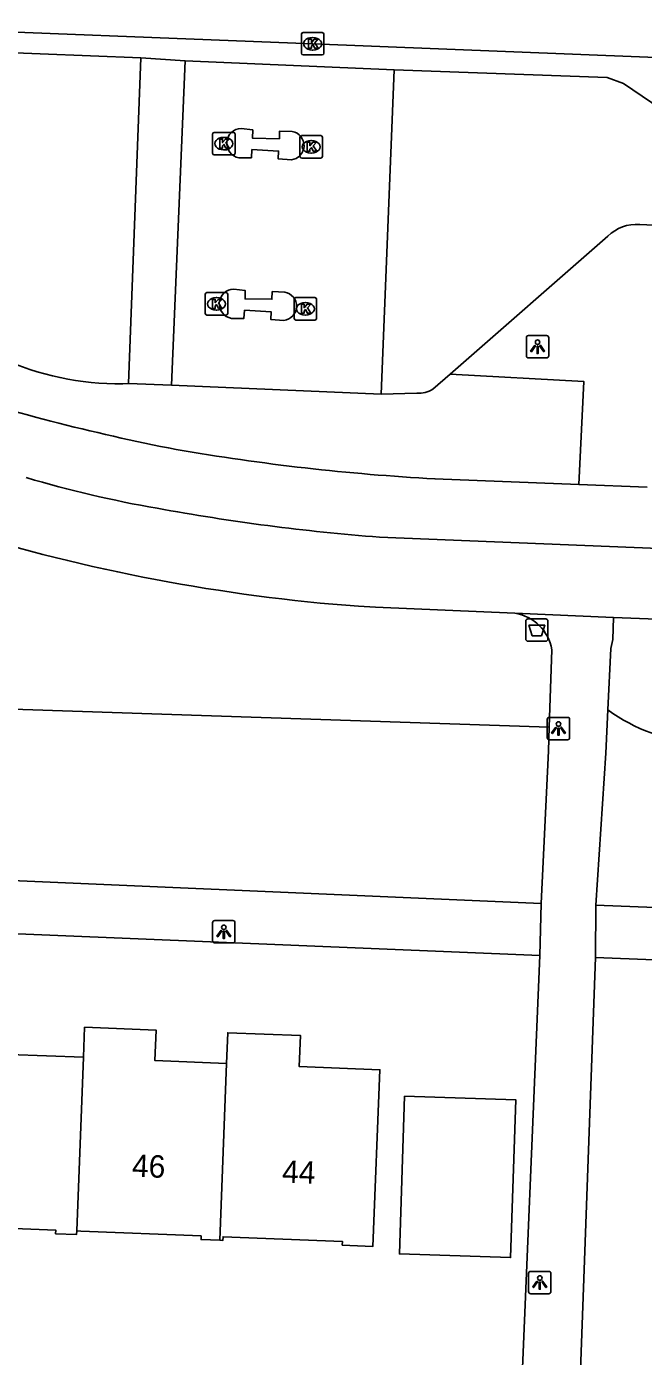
# Model space of a CAD drawing. Extents: x 161355 to 162026, y 386504 to 387459.
# Drawn here: x 161506.1 to 161533.7, y 387396.4 to 387455.8 of the extents above; entities that cross this region are included whole.
import ezdxf

# ---------------------------------------------------------------- set-up
doc = ezdxf.new("R2010")
doc.units = 0
for name, color, linetype in [('IMGEO_Afvalbak', 7, 'Continuous'), ('IMGEO_Fietspad_gesloten', 7, 'Continuous'), ('IMGEO_Groenvoorziening', 7, 'Continuous'), ('IMGEO_Kolk', 7, 'Continuous'), ('IMGEO_Lichtpunt', 7, 'Continuous'), ('IMGEO_Pand', 7, 'Continuous'), ('IMGEO_Pand_nummerreeks', 7, 'Continuous'), ('IMGEO_Rijbaan_lokaal_gesloten', 7, 'Continuous'), ('IMGEO_Rijbaan_lokaal_open', 7, 'Continuous'), ('IMGEO_Voetpad_open', 7, 'Continuous')]:
    doc.layers.add(name, color=color, linetype=linetype)

msp = doc.modelspace()

# ---------------------------------------------------------------- linework, layer by layer
at = {"layer": 'IMGEO_Afvalbak'}
for p, q in [((161528.416, 387428.43), (161528.416, 387429.23)), ((161528.416, 387429.23), (161528.416, 387428.43)), ((161528.516, 387429.33), (161529.306, 387429.33)), ((161529.306, 387429.33), (161528.516, 387429.33)), ((161529.406, 387429.23), (161529.406, 387428.43)), ((161529.406, 387428.43), (161529.406, 387429.23)), ((161529.306, 387428.33), (161528.516, 387428.33)), ((161528.516, 387428.33), (161529.306, 387428.33))]:
    msp.add_line(p, q, dxfattribs=at)
msp.add_lwpolyline([(161528.559, 387429.044), (161529.263, 387429.044), (161529.114, 387428.574), (161528.708, 387428.574), (161528.559, 387429.044)], dxfattribs=at)
for centre, start, end in [((161528.516, 387429.23), 90, 180), ((161528.516, 387429.23), 90, 180), ((161529.306, 387429.23), 0, 90), ((161529.306, 387429.23), 360, 90), ((161528.516, 387428.43), 180, 270), ((161528.516, 387428.43), 180, 270), ((161529.306, 387428.43), 270, 0), ((161529.306, 387428.43), 270, 0)]:
    msp.add_arc(centre, 0.1, start, end, dxfattribs=at)
at = {"layer": 'IMGEO_Fietspad_gesloten'}
for points in [[(161530.79, 387435.322), (161524.366, 387435.573)], [(161533.831, 387435.204), (161530.79, 387435.322)], [(161550.847, 387431.802), (161521.887, 387432.975)]]:
    msp.add_lwpolyline(points, dxfattribs=at)
for centre, radius, start, end in [((161531.28, 387531.263), 96.168, 252.09859, 258.93178), ((161529.933, 387536.124), 100.704, 260.21511, 266.83121), ((161520.95, 387485.839), 52.352, 253.55405, 260.11709), ((161529.21, 387528.19), 95.496, 259.59553, 265.60189)]:
    msp.add_arc(centre, radius, start, end, dxfattribs=at)
at = {"layer": 'IMGEO_Groenvoorziening'}
msp.add_lwpolyline([(161499.222, 387425.612), (161503.74, 387425.354), (161529.46, 387424.501)], dxfattribs=at)
msp.add_arc((161536.51, 387431.29), 7.475, 233.6324, 267.37619, dxfattribs=at)
at = {"layer": 'IMGEO_Kolk'}
for p, q in [((161518.481, 387455.486), (161519.333, 387455.486)), ((161518.406, 387454.56), (161518.406, 387455.412)), ((161518.894, 387455.266), (161518.919, 387455.266)), ((161519.407, 387455.412), (161519.407, 387454.56)), ((161519.333, 387454.486), (161518.481, 387454.486)), ((161518.917, 387454.706), (161518.892, 387454.706)), ((161514.442, 387450.105), (161514.442, 387450.957)), ((161514.517, 387451.031), (161515.369, 387451.031)), ((161514.93, 387450.811), (161514.955, 387450.811)), ((161515.443, 387450.957), (161515.443, 387450.105)), ((161518.341, 387449.963), (161518.341, 387450.815)), ((161518.416, 387450.889), (161519.268, 387450.889)), ((161519.342, 387450.815), (161519.342, 387449.963)), ((161514.953, 387450.251), (161514.928, 387450.251)), ((161518.852, 387450.109), (161518.827, 387450.109)), ((161518.829, 387450.669), (161518.854, 387450.669)), ((161515.369, 387450.031), (161514.517, 387450.031)), ((161519.268, 387449.889), (161518.416, 387449.889)), ((161514.114, 387442.957), (161514.114, 387443.809)), ((161514.189, 387443.883), (161515.041, 387443.883)), ((161514.602, 387443.663), (161514.627, 387443.663)), ((161515.115, 387443.809), (161515.115, 387442.957)), ((161518.081, 387442.736), (161518.081, 387443.588)), ((161518.156, 387443.662), (161519.008, 387443.662)), ((161519.082, 387443.588), (161519.082, 387442.736)), ((161514.625, 387443.103), (161514.6, 387443.103)), ((161518.569, 387443.442), (161518.594, 387443.442)), ((161515.041, 387442.883), (161514.189, 387442.883)), ((161519.008, 387442.662), (161518.156, 387442.662)), ((161518.592, 387442.882), (161518.567, 387442.882))]:
    msp.add_line(p, q, dxfattribs=at)
for points in [[(161518.481, 387455.486), (161519.333, 387455.486)], [(161518.406, 387454.56), (161518.406, 387455.412)], [(161518.727, 387455.186), (161518.85, 387455.186), (161518.85, 387455.035), (161518.98, 387455.186), (161519.144, 387455.186), (161518.998, 387455.035), (161519.151, 387454.786), (161518.999, 387454.786), (161518.914, 387454.95), (161518.85, 387454.883), (161518.85, 387454.786), (161518.727, 387454.786), (161518.727, 387455.186)], [(161519.407, 387455.412), (161519.407, 387454.56)], [(161519.333, 387454.486), (161518.481, 387454.486)], [(161514.442, 387450.105), (161514.442, 387450.957)], [(161514.517, 387451.031), (161515.369, 387451.031)], [(161514.763, 387450.731), (161514.886, 387450.731), (161514.886, 387450.58), (161515.016, 387450.731), (161515.18, 387450.731), (161515.034, 387450.58), (161515.187, 387450.331), (161515.035, 387450.331), (161514.95, 387450.495), (161514.886, 387450.428), (161514.886, 387450.331), (161514.763, 387450.331), (161514.763, 387450.731)], [(161515.443, 387450.957), (161515.443, 387450.105)], [(161518.341, 387449.963), (161518.341, 387450.815)], [(161518.416, 387450.889), (161519.268, 387450.889)], [(161519.342, 387450.815), (161519.342, 387449.963)], [(161518.662, 387450.589), (161518.785, 387450.589), (161518.785, 387450.438), (161518.915, 387450.589), (161519.079, 387450.589), (161518.933, 387450.438), (161519.086, 387450.189), (161518.934, 387450.189), (161518.849, 387450.353), (161518.785, 387450.286), (161518.785, 387450.189), (161518.662, 387450.189), (161518.662, 387450.589)], [(161515.369, 387450.031), (161514.517, 387450.031)], [(161519.268, 387449.889), (161518.416, 387449.889)], [(161514.114, 387442.957), (161514.114, 387443.809)], [(161514.189, 387443.883), (161515.041, 387443.883)], [(161514.435, 387443.583), (161514.558, 387443.583), (161514.558, 387443.432), (161514.688, 387443.583), (161514.852, 387443.583), (161514.706, 387443.432), (161514.859, 387443.183), (161514.707, 387443.183), (161514.622, 387443.347), (161514.558, 387443.28), (161514.558, 387443.183), (161514.435, 387443.183), (161514.435, 387443.583)], [(161515.115, 387443.809), (161515.115, 387442.957)], [(161518.081, 387442.736), (161518.081, 387443.588)], [(161518.156, 387443.662), (161519.008, 387443.662)], [(161519.082, 387443.588), (161519.082, 387442.736)], [(161518.402, 387443.362), (161518.525, 387443.362), (161518.525, 387443.211), (161518.655, 387443.362), (161518.819, 387443.362), (161518.673, 387443.211), (161518.826, 387442.962), (161518.674, 387442.962), (161518.589, 387443.126), (161518.525, 387443.059), (161518.525, 387442.962), (161518.402, 387442.962), (161518.402, 387443.362)], [(161515.041, 387442.883), (161514.189, 387442.883)], [(161519.008, 387442.662), (161518.156, 387442.662)]]:
    msp.add_lwpolyline(points, dxfattribs=at)
for centre, start, end in [((161518.483, 387455.41), 91.55205, 178.44795), ((161518.483, 387455.41), 91.55205, 178.44795), ((161519.331, 387455.41), 1.55205, 88.44795), ((161519.331, 387455.41), 1.55205, 88.44795), ((161518.483, 387454.562), 181.55205, 268.44795), ((161518.483, 387454.562), 181.55205, 268.44795), ((161519.331, 387454.562), 271.55205, 358.44795), ((161519.331, 387454.562), 271.55205, 358.44795), ((161514.519, 387450.955), 91.55205, 178.44795), ((161514.519, 387450.955), 91.55205, 178.44795), ((161515.367, 387450.955), 1.55205, 88.44795), ((161515.367, 387450.955), 1.55205, 88.44795), ((161518.418, 387450.813), 91.55205, 178.44795), ((161518.418, 387450.813), 91.55205, 178.44795), ((161519.266, 387450.813), 1.55205, 88.44795), ((161519.266, 387450.813), 1.55205, 88.44795), ((161514.519, 387450.107), 181.55205, 268.44795), ((161514.519, 387450.107), 181.55205, 268.44795), ((161515.367, 387450.107), 271.55205, 358.44795), ((161515.367, 387450.107), 271.55205, 358.44795), ((161518.418, 387449.965), 181.55205, 268.44795), ((161518.418, 387449.965), 181.55205, 268.44795), ((161519.266, 387449.965), 271.55205, 358.44795), ((161519.266, 387449.965), 271.55205, 358.44795), ((161514.191, 387443.807), 91.55205, 178.44795), ((161514.191, 387443.807), 91.55205, 178.44795), ((161515.039, 387443.807), 1.55205, 88.44795), ((161515.039, 387443.807), 1.55205, 88.44795), ((161518.158, 387443.586), 91.55205, 178.44795), ((161518.158, 387443.586), 91.55205, 178.44795), ((161519.006, 387443.586), 1.55205, 88.44795), ((161519.006, 387443.586), 1.55205, 88.44795), ((161514.191, 387442.959), 181.55205, 268.44795), ((161514.191, 387442.959), 181.55205, 268.44795), ((161515.039, 387442.959), 271.55205, 358.44795), ((161515.039, 387442.959), 271.55205, 358.44795), ((161518.158, 387442.738), 181.55205, 268.44795), ((161518.158, 387442.738), 181.55205, 268.44795), ((161519.006, 387442.738), 271.55205, 358.44795), ((161519.006, 387442.738), 271.55205, 358.44795)]:
    msp.add_arc(centre, 0.0765, start, end, dxfattribs=at)
for centre, major_axis, ratio, start_param, end_param in [((161518.893, 387454.986), (-0.387, 0.002), 0.722429, 4.712389, 7.853982), ((161518.918, 387454.986), (-0.39, 0.002), 0.717154, 1.570796, 4.712389), ((161514.929, 387450.531), (-0.387, 0.002), 0.722429, 4.712389, 7.853982), ((161514.954, 387450.531), (-0.39, 0.002), 0.717154, 1.570796, 4.712389), ((161518.828, 387450.389), (-0.387, 0.002), 0.722429, 4.712389, 7.853982), ((161518.853, 387450.389), (-0.39, 0.002), 0.717154, 1.570796, 4.712389), ((161514.601, 387443.383), (-0.387, 0.002), 0.722429, 4.712389, 7.853982), ((161514.626, 387443.383), (-0.39, 0.002), 0.717154, 1.570796, 4.712389), ((161518.568, 387443.162), (-0.387, 0.002), 0.722429, 4.712389, 7.853982), ((161518.593, 387443.162), (-0.39, 0.002), 0.717154, 1.570796, 4.712389)]:
    msp.add_ellipse(centre, major_axis=major_axis, ratio=ratio, start_param=start_param, end_param=end_param, dxfattribs=at)
at = {"layer": 'IMGEO_Lichtpunt'}
for p, q in [((161528.444, 387441.873), (161528.444, 387441.066)), ((161528.444, 387441.873), (161528.444, 387441.066)), ((161529.346, 387441.968), (161528.538, 387441.968)), ((161529.346, 387441.968), (161528.538, 387441.968)), ((161529.44, 387441.066), (161529.44, 387441.873)), ((161529.44, 387441.066), (161529.44, 387441.873)), ((161528.538, 387440.972), (161529.346, 387440.972)), ((161528.538, 387440.972), (161529.346, 387440.972)), ((161529.378, 387424.841), (161529.378, 387424.034)), ((161529.378, 387424.841), (161529.378, 387424.034)), ((161530.28, 387424.936), (161529.472, 387424.936)), ((161530.28, 387424.936), (161529.472, 387424.936)), ((161530.374, 387424.034), (161530.374, 387424.841)), ((161530.374, 387424.034), (161530.374, 387424.841)), ((161529.472, 387423.94), (161530.28, 387423.94)), ((161529.472, 387423.94), (161530.28, 387423.94)), ((161514.444, 387415.774), (161514.444, 387414.967)), ((161514.444, 387415.774), (161514.444, 387414.967)), ((161515.346, 387415.869), (161514.538, 387415.869)), ((161515.346, 387415.869), (161514.538, 387415.869)), ((161515.44, 387414.967), (161515.44, 387415.774)), ((161515.44, 387414.967), (161515.44, 387415.774)), ((161514.538, 387414.873), (161515.346, 387414.873)), ((161514.538, 387414.873), (161515.346, 387414.873)), ((161528.543, 387400.126), (161528.543, 387399.319)), ((161528.543, 387400.126), (161528.543, 387399.319)), ((161529.445, 387400.221), (161528.637, 387400.221)), ((161529.445, 387400.221), (161528.637, 387400.221)), ((161529.539, 387399.319), (161529.539, 387400.126)), ((161529.539, 387399.319), (161529.539, 387400.126)), ((161528.637, 387399.225), (161529.445, 387399.225)), ((161528.637, 387399.225), (161529.445, 387399.225))]:
    msp.add_line(p, q, dxfattribs=at)
for points in [[(161528.818, 387441.537), (161528.857, 387441.509), (161528.669, 387441.247), (161528.631, 387441.274), (161528.818, 387441.537)], [(161528.92, 387441.489), (161528.967, 387441.489), (161528.967, 387441.167), (161528.92, 387441.167), (161528.92, 387441.489)], [(161529.03, 387441.509), (161529.068, 387441.536), (161529.255, 387441.274), (161529.216, 387441.246), (161529.03, 387441.509)], [(161529.752, 387424.505), (161529.791, 387424.477), (161529.603, 387424.215), (161529.565, 387424.242), (161529.752, 387424.505)], [(161529.854, 387424.457), (161529.901, 387424.457), (161529.901, 387424.135), (161529.854, 387424.135), (161529.854, 387424.457)], [(161529.964, 387424.477), (161530.002, 387424.504), (161530.189, 387424.242), (161530.15, 387424.214), (161529.964, 387424.477)], [(161514.818, 387415.438), (161514.857, 387415.41), (161514.669, 387415.148), (161514.631, 387415.175), (161514.818, 387415.438)], [(161514.92, 387415.39), (161514.967, 387415.39), (161514.967, 387415.068), (161514.92, 387415.068), (161514.92, 387415.39)], [(161515.03, 387415.41), (161515.068, 387415.437), (161515.255, 387415.175), (161515.216, 387415.147), (161515.03, 387415.41)], [(161528.917, 387399.79), (161528.956, 387399.762), (161528.768, 387399.5), (161528.73, 387399.527), (161528.917, 387399.79)], [(161529.019, 387399.742), (161529.066, 387399.742), (161529.066, 387399.42), (161529.019, 387399.42), (161529.019, 387399.742)], [(161529.129, 387399.762), (161529.167, 387399.789), (161529.354, 387399.527), (161529.315, 387399.499), (161529.129, 387399.762)]]:
    msp.add_lwpolyline(points, dxfattribs=at)
for centre in [(161528.943, 387441.671), (161529.877, 387424.639), (161514.943, 387415.572), (161529.042, 387399.924)]:
    msp.add_circle(centre, 0.0994, dxfattribs=at)
for centre, start, end in [((161528.538, 387441.873), 90, 180), ((161528.538, 387441.873), 90, 180), ((161529.346, 387441.873), 0, 90), ((161529.346, 387441.873), 0, 90), ((161528.538, 387441.066), 180, 270), ((161528.538, 387441.066), 180, 270), ((161529.346, 387441.066), 270, 0), ((161529.346, 387441.066), 270, 360), ((161529.472, 387424.841), 90, 180), ((161529.472, 387424.841), 90, 180), ((161530.28, 387424.841), 0, 90), ((161530.28, 387424.841), 0, 90), ((161529.472, 387424.034), 180, 270), ((161529.472, 387424.034), 180, 270), ((161530.28, 387424.034), 270, 0), ((161530.28, 387424.034), 270, 360), ((161514.538, 387415.774), 90, 180), ((161514.538, 387415.774), 90, 180), ((161515.346, 387415.774), 0, 90), ((161515.346, 387415.774), 0, 90), ((161514.538, 387414.967), 180, 270), ((161514.538, 387414.967), 180, 270), ((161515.346, 387414.967), 270, 0), ((161515.346, 387414.967), 270, 360), ((161528.637, 387400.126), 90, 180), ((161528.637, 387400.126), 90, 180), ((161529.445, 387400.126), 0, 90), ((161529.445, 387400.126), 0, 90), ((161528.637, 387399.319), 180, 270), ((161528.637, 387399.319), 180, 270), ((161529.445, 387399.319), 270, 0), ((161529.445, 387399.319), 270, 360)]:
    msp.add_arc(centre, 0.0946, start, end, dxfattribs=at)
at = {"layer": 'IMGEO_Pand'}
for points in [[(161502.175, 387410.075), (161502.228, 387411.376), (161505.437, 387411.248), (161505.383, 387409.901), (161508.678, 387409.769)], [(161508.678, 387409.769), (161508.731, 387411.112), (161511.92, 387410.984), (161511.865, 387409.621), (161515.063, 387409.493)], [(161515.063, 387409.493), (161515.118, 387410.869), (161518.366, 387410.74), (161518.311, 387409.359), (161521.911, 387409.215), (161521.595, 387401.335), (161520.23, 387401.39), (161520.237, 387401.553), (161514.908, 387401.766), (161514.902, 387401.602), (161514.757, 387401.608)], [(161508.378, 387402.023), (161508.678, 387409.769)], [(161515.063, 387409.493), (161514.757, 387401.608)], [(161523.009, 387408.038), (161527.972, 387407.876), (161527.742, 387400.837), (161522.779, 387401), (161523.009, 387408.038)], [(161508.378, 387402.023), (161508.372, 387401.865), (161507.431, 387401.902), (161507.44, 387402.064), (161501.872, 387402.286)], [(161514.757, 387401.608), (161513.924, 387401.641), (161513.93, 387401.8), (161508.567, 387402.015), (161508.378, 387402.023)]]:
    msp.add_lwpolyline(points, dxfattribs=at)
at = {"layer": 'IMGEO_Rijbaan_lokaal_gesloten'}
msp.add_lwpolyline([(161499.444, 387455.752), (161500, 387455.73), (161518.907, 387454.987), (161539.467, 387454.167), (161559.197, 387453.359)], dxfattribs=at)
at = {"layer": 'IMGEO_Rijbaan_lokaal_open'}
for points in [[(161499.889, 387454.807), (161500, 387454.803), (161511.237, 387454.355)], [(161511.237, 387454.355), (161510.683, 387439.826)], [(161511.237, 387454.355), (161513.211, 387454.223)], [(161512.61, 387439.758), (161513.211, 387454.223)], [(161513.211, 387454.223), (161522.54, 387453.825)], [(161522.54, 387453.825), (161521.96, 387439.357)], [(161522.54, 387453.825), (161532.045, 387453.475), (161532.773, 387453.217), (161535.278, 387451.524), (161536.01, 387451.288), (161538.258, 387451.202), (161553.456, 387450.577), (161554.487, 387450.593), (161555.262, 387450.735), (161558.952, 387452.485)], [(161517.996, 387451.073), (161517.434, 387451.092), (161517.423, 387450.75), (161516.222, 387450.77), (161516.234, 387451.143), (161515.718, 387451.205)], [(161515.616, 387449.901), (161516.174, 387449.899), (161516.198, 387450.266), (161517.387, 387450.195), (161517.367, 387449.854), (161517.955, 387449.807)], [(161547.156, 387446.275), (161533.502, 387446.923)], [(161532.079, 387446.399), (161525.039, 387440.242)], [(161517.663, 387443.908), (161517.101, 387443.927), (161517.09, 387443.585), (161515.889, 387443.605), (161515.901, 387443.978), (161515.385, 387444.04)], [(161515.283, 387442.736), (161515.841, 387442.734), (161515.865, 387443.101), (161517.054, 387443.03), (161517.034, 387442.689), (161517.622, 387442.642)], [(161524.272, 387439.571), (161525.039, 387440.242)], [(161510.435, 387439.82), (161510.683, 387439.826)], [(161510.683, 387439.826), (161512.61, 387439.758)], [(161512.61, 387439.758), (161521.96, 387439.357)], [(161521.96, 387439.357), (161523.559, 387439.397)]]:
    msp.add_lwpolyline(points, dxfattribs=at)
for centre, radius, start, end in [((161515.728, 387450.548), 0.657, 90.86109, 260.19367), ((161517.881, 387450.443), 0.64, 276.63646, 79.65374), ((161533.351, 387445.139), 1.79, 85.1591, 135.27196), ((161510.279, 387452.638), 12.819, 220.54041, 270.69735), ((161515.395, 387443.383), 0.657, 90.86109, 260.19367), ((161517.548, 387443.278), 0.64, 276.63646, 79.65374), ((161523.612, 387440.728), 1.332, 267.72512, 299.7036)]:
    msp.add_arc(centre, radius, start, end, dxfattribs=at)
at = {"layer": 'IMGEO_Voetpad_open'}
for points in [[(161525.039, 387440.242), (161531.015, 387439.916), (161530.79, 387435.322)], [(161520.952, 387429.889), (161521.718, 387429.858), (161527.927, 387429.583)], [(161532.339, 387429.397), (161527.927, 387429.583)], [(161532.078, 387425.271), (161532.212, 387428.003), (161532.309, 387428.409), (161532.339, 387429.397)], [(161532.339, 387429.397), (161548.547, 387428.759), (161550.868, 387428.648)], [(161529.577, 387427.95), (161529.46, 387424.501)], [(161531.548, 387416.555), (161531.984, 387423.34), (161532.078, 387425.271)], [(161529.46, 387424.501), (161529.424, 387423.439), (161529.101, 387416.63)], [(161464.073, 387419.511), (161500, 387417.889), (161529.101, 387416.63)], [(161529.048, 387414.318), (161500, 387415.522), (161475.224, 387416.549), (161474.909, 387416.561)], [(161529.101, 387416.63), (161529.048, 387414.318)], [(161531.527, 387414.224), (161531.548, 387416.555)], [(161652.45, 387411.813), (161622.17, 387413.001), (161531.548, 387416.555)], [(161526.168, 387390.907), (161526.337, 387390.908), (161526.506, 387390.924), (161526.673, 387390.955), (161526.836, 387391), (161526.994, 387391.06), (161527.147, 387391.134), (161527.292, 387391.222), (161527.429, 387391.322), (161527.556, 387391.433), (161527.673, 387391.556), (161527.778, 387391.689), (161527.872, 387391.83), (161527.952, 387391.979), (161528.018, 387392.135), (161528.07, 387392.296), (161528.108, 387392.462), (161528.131, 387392.629), (161528.137, 387392.72), (161529.048, 387414.318)], [(161532.354, 387390.78), (161532.29, 387390.784), (161532.14, 387390.804), (161531.992, 387390.837), (161531.848, 387390.883), (161531.709, 387390.942), (161531.575, 387391.013), (161531.448, 387391.095), (161531.329, 387391.189), (161531.219, 387391.293), (161531.119, 387391.406), (161531.029, 387391.528), (161530.951, 387391.657), (161530.884, 387391.793), (161530.83, 387391.934), (161530.789, 387392.08), (161530.76, 387392.228), (161530.745, 387392.379), (161530.744, 387392.53), (161531.527, 387414.224)], [(161531.527, 387414.224), (161590.228, 387411.885)]]:
    msp.add_lwpolyline(points, dxfattribs=at)
for centre, radius, start, end in [((161527.061, 387511.106), 81.446, 252.82618, 265.69857), ((161527.628, 387427.631), 1.975, 9.30039, 81.29299)]:
    msp.add_arc(centre, radius, start, end, dxfattribs=at)

# ---------------------------------------------------------------- texts
at = {"layer": 'IMGEO_Pand_nummerreeks'}
for s, rotation, p in [('46', 357.70817, (161510.828, 387404.447)), ('44', 357.7139, (161517.529, 387404.184))]:
    msp.add_text(s, height=1, rotation=rotation, dxfattribs=at).set_placement(p)

doc.saveas('drawing.dxf')
